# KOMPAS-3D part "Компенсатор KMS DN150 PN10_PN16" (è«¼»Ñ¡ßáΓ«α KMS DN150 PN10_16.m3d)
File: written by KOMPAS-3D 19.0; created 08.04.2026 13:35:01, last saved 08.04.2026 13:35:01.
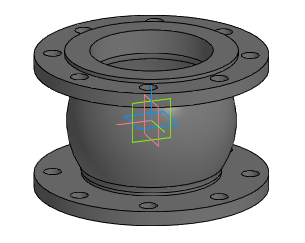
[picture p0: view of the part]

Document properties: Автор: Энергия; Полное имя файла: Z:\3.Личные\kachalov\3d для проектировщиков\7.1 Компенсатор\stp_Компенсатор KSM\Компенсатор KMS DN150 PN10_16.m3d

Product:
- Part/product: Компенсатор KMS DN150 PN10_PN16

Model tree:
1. Операция без истории:1  (labels: Компенсатор KMS DN150 PN10_PN16)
